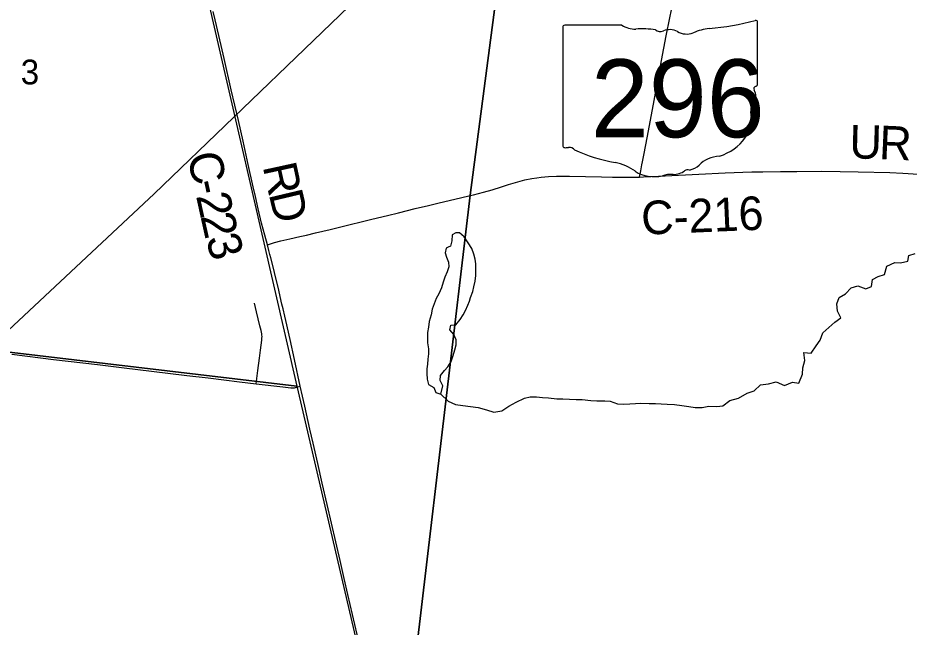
# Model space of a CAD drawing. Extents: x 0 to 1101, y 0 to 440.
# Drawn here: x 844.169 to 845.677, y 370.06 to 371.091 of the extents above; entities that cross this region are included whole.
import ezdxf

# ---------------------------------------------------------------- set-up
doc = ezdxf.new("R2010")
doc.units = 0
for name, color, linetype in [('GM_X_County_Road', 7, 'Continuous'), ('GM_X_County_Road_Text', 7, 'Continuous'), ('GM_X_Minor_Lake', 7, 'Continuous'), ('GM_X_Minor_River', 7, 'Continuous'), ('GM_X_Rail_Line', 7, 'Continuous'), ('GM_X_Section', 7, 'Continuous'), ('GM_X_Section_Text', 7, 'Continuous'), ('GM_X_State_Location', 7, 'Continuous'), ('GM_X_State_Route', 7, 'Continuous'), ('GM_X_State_Shield', 7, 'Continuous'), ('GM_X_Township', 7, 'Continuous'), ('GM_X_Township_Road', 7, 'Continuous')]:
    doc.layers.add(name, color=color, linetype=linetype)

msp = doc.modelspace()

# ---------------------------------------------------------------- linework, layer by layer
at = {"layer": 'GM_X_County_Road'}
for points in [[(844.5913, 370.7074), (844.5869, 370.7236), (844.5814, 370.744), (844.5758, 370.7682), (844.5712, 370.7888), (844.5675, 370.8052), (844.5588, 370.8433), (844.5503, 370.8828), (844.5423, 370.9179), (844.5302, 370.9694), (844.5179, 371.0226), (844.5129, 371.0444), (844.5028, 371.088), (844.4994, 371.1022)], [(845.221, 370.8219), (845.2279, 370.8223), (845.2531, 370.8235), (845.3212, 370.8271), (845.3658, 370.829), (845.4111, 370.8307), (845.4297, 370.8309), (845.4595, 370.8311), (845.4875, 370.8314), (845.5291, 370.8317), (845.5608, 370.8315), (845.5913, 370.831), (845.6447, 370.8296), (845.6665, 370.8285), (845.7198, 370.825)]]:
    msp.add_lwpolyline(points, dxfattribs=at)
at = {"layer": 'GM_X_Minor_Lake'}
for points in [[(844.8847, 370.4544), (844.888, 370.4684), (844.8839, 370.4776), (844.8844, 370.4863), (844.891, 370.4945), (844.8964, 370.5005), (844.9022, 370.5096), (844.9058, 370.5202), (844.9086, 370.5296), (844.9106, 370.5379), (844.9107, 370.5467), (844.9067, 370.5555), (844.9003, 370.5632), (844.902, 370.5715), (844.9103, 370.5717), (844.9173, 370.5811), (844.9227, 370.5887), (844.9263, 370.5962), (844.9306, 370.6053), (844.9333, 370.6117), (844.9353, 370.6181), (844.9389, 370.6283), (844.9409, 370.6363), (844.9429, 370.6457), (844.9438, 370.6556), (844.9441, 370.6753), (844.9431, 370.6829), (844.9409, 370.6913), (844.9372, 370.7009), (844.9309, 370.7108), (844.9242, 370.7208), (844.9164, 370.7273), (844.9103, 370.7278), (844.9042, 370.7241), (844.9036, 370.7139), (844.9012, 370.7052), (844.8973, 370.7034)], [(844.8973, 370.7034), (844.8936, 370.7018), (844.8923, 370.6939), (844.8945, 370.6863), (844.8978, 370.6779), (844.8985, 370.6699), (844.8957, 370.6616), (844.8914, 370.6525), (844.889, 370.6442), (844.8858, 370.6344), (844.8815, 370.6245), (844.8772, 370.6163), (844.8733, 370.6072), (844.8701, 370.5985), (844.8684, 370.5887), (844.8652, 370.5773), (844.864, 370.5678), (844.8623, 370.5591), (844.8621, 370.5413), (844.8638, 370.5314), (844.8637, 370.523), (844.8628, 370.5135), (844.8623, 370.5052), (844.8614, 370.4972), (844.8609, 370.4893), (844.8616, 370.4801), (844.8641, 370.471), (844.8731, 370.4656), (844.8764, 370.4575), (844.8847, 370.4544)]]:
    msp.add_lwpolyline(points, dxfattribs=at)
at = {"layer": 'GM_X_Minor_River'}
msp.add_lwpolyline([(844.8847, 370.4544), (844.8975, 370.4428), (844.9095, 370.4369), (844.9221, 370.4353), (844.9349, 370.4336), (844.9482, 370.4319), (844.9622, 370.4279), (844.9747, 370.4243), (844.988, 370.4264), (844.9999, 370.4342), (845.0125, 370.4412), (845.0266, 370.4479), (845.0362, 370.45), (845.0468, 370.4499), (845.057, 370.449), (845.0673, 370.4481), (845.0813, 370.4467), (845.0915, 370.4466), (845.1025, 370.4461), (845.1139, 370.4455), (845.1238, 370.4454), (845.1389, 370.4437), (845.1488, 370.4431), (845.1621, 370.4433), (845.1716, 370.4424), (845.184, 370.4381), (845.1935, 370.4376), (845.2045, 370.4382), (845.214, 370.4388), (845.2235, 370.4391), (845.2372, 370.4385), (845.2482, 370.4387), (845.2577, 370.4382), (845.2676, 370.4377), (845.2801, 370.4368), (845.2926, 370.4355), (845.3047, 370.4334), (845.3153, 370.4317), (845.3271, 370.432), (845.3385, 370.4341), (845.3518, 370.4339), (845.362, 370.4345), (845.3739, 370.4439), (845.3888, 370.4478), (845.403, 370.456), (845.4152, 370.4604), (845.426, 370.4701), (845.4396, 370.4722), (845.4522, 370.4751), (845.4662, 370.4692), (845.4799, 370.4747), (845.4905, 370.4734), (845.4968, 370.4881), (845.4977, 370.4991), (845.5006, 370.5116), (845.4989, 370.525), (845.5118, 370.524), (845.5199, 370.5361), (845.5265, 370.5459), (845.5312, 370.5583), (845.5416, 370.5673), (845.5516, 370.5763), (845.5616, 370.5837), (845.5561, 370.5952), (845.5551, 370.6074), (845.5587, 370.618), (845.5694, 370.6246), (845.5794, 370.6344), (845.5908, 370.6376), (845.6041, 370.6329), (845.6136, 370.6366), (845.6153, 370.6483), (845.6252, 370.6535), (845.6355, 370.6568), (845.6395, 370.6712), (845.6533, 370.6774), (845.6628, 370.6769), (845.675, 370.6798), (845.677, 370.6893), (845.6877, 370.6925)], dxfattribs=at)
at = {"layer": 'GM_X_Rail_Line'}
msp.add_lwpolyline([(844.1346, 370.5459), (844.3997, 370.7937), (844.8041, 371.1833), (845.1901, 371.5461), (845.4225, 371.7708), (845.5333, 371.8771), (845.5894, 371.9309), (845.6284, 371.9639), (845.6782, 371.9983), (845.7357, 372.0303), (845.789, 372.0514), (845.8324, 372.0633), (845.8796, 372.0733), (846.2786, 372.1146), (846.3759, 372.1225), (846.4631, 372.1257), (846.5327, 372.1208), (846.59, 372.1143), (846.7044, 372.0937), (846.8234, 372.0596), (847.2573, 371.9407)], dxfattribs=at)
at = {"layer": 'GM_X_Section'}
for points in [[(843.9352, 371.6074), (844.3881, 371.5681), (844.393, 371.547), (844.6414, 370.468), (843.8246, 370.5643)], [(843.8246, 370.5643), (844.6414, 370.468), (844.8139, 369.7283), (844.7837, 369.4496), (843.7228, 369.5896)]]:
    msp.add_lwpolyline(points, close=True, dxfattribs=at)
at = {"layer": 'GM_X_State_Route'}
for points in [[(844.9345, 370.7908), (844.9399, 370.7921), (844.9568, 370.7962), (844.9717, 370.8003), (844.9876, 370.8055), (844.9994, 370.8094), (845.0149, 370.8141), (845.027, 370.8171), (845.039, 370.8195), (845.0473, 370.8208), (845.0544, 370.8217), (845.0607, 370.8223), (845.0671, 370.8228), (845.0808, 370.8233), (845.1026, 370.8232), (845.1566, 370.8222), (845.1755, 370.8219), (845.1928, 370.8218), (845.2111, 370.8217), (845.221, 370.8219), (845.2231, 370.8323), (845.2252, 370.8428), (845.2262, 370.8477), (845.2282, 370.8588), (845.2344, 370.8911), (845.2457, 370.9516), (845.2583, 371.0194), (845.2661, 371.0609), (845.2722, 371.0914), (845.2752, 371.1048)], [(844.5913, 370.7074), (844.6036, 370.711), (844.614, 370.7138), (844.6294, 370.7173), (844.646, 370.7212), (844.6575, 370.7238), (844.6729, 370.7275), (844.6973, 370.7334), (844.7359, 370.7428), (844.7457, 370.7453), (844.7683, 370.7507), (844.7944, 370.757), (844.8131, 370.7613), (844.8415, 370.7686), (844.8638, 370.7739), (844.8818, 370.7783), (844.9181, 370.787), (844.9345, 370.7908)], [(844.1588, 370.5223), (844.2291, 370.5134), (844.3037, 370.5045), (844.3488, 370.4992), (844.395, 370.4937), (844.4548, 370.4861), (844.4912, 370.4819), (844.5443, 370.4755), (844.5723, 370.4721), (844.6173, 370.4667), (844.6309, 370.4655), (844.6349, 370.4654), (844.6372, 370.4655), (844.6391, 370.4659), (844.6424, 370.4668), (844.6466, 370.4682), (844.6373, 370.5133), (844.6298, 370.5472), (844.6225, 370.5793), (844.6208, 370.5865), (844.6178, 370.5992), (844.616, 370.607), (844.6094, 370.6354), (844.6039, 370.6577), (844.6026, 370.6631), (844.5969, 370.6854), (844.5955, 370.6908), (844.5938, 370.6978), (844.5913, 370.7074)], [(844.8109, 369.7447), (844.8096, 369.7503), (844.7936, 369.8225), (844.7813, 369.8796), (844.743, 370.048), (844.7274, 370.1152), (844.7213, 370.1425), (844.7144, 370.1728), (844.6922, 370.2678), (844.6841, 370.3036), (844.6765, 370.3369), (844.6685, 370.3714), (844.6632, 370.395), (844.6544, 370.4344), (844.6466, 370.4682)]]:
    msp.add_lwpolyline(points, dxfattribs=at)
at = {"layer": 'GM_X_State_Shield'}
for p, q in [((845.0913, 371.0753), (845.0913, 370.8752)), ((845.1911, 371.0788), (845.0946, 371.0788)), ((845.4209, 370.979), (845.4209, 371.0837)), ((845.4209, 370.9791), (845.4209, 370.979))]:
    msp.add_line(p, q, dxfattribs=at)
for centre, major_axis, start_param, end_param in [((845.0951, 371.0758), (0.00382, 0), 1.712693, 3.28349), ((845.2141, 371.102), (0.037, 0), 4.042523, 4.731795), ((845.3035, 371.3516), (0.3495, 0), 4.814394, 5.042369), ((845.4173, 371.0842), (0.00367, 0), 6.141152, 7.989035), ((845.2264, 370.9664), (0.133, 0), 1.404758, 1.657858), ((845.2565, 371.0768), (0.0107, 0), 3.836095, 5.185415), ((845.2722, 371.0537), (0.0222, 0), 0.950623, 2.079405), ((845.3009, 371.0854), (0.0267, 0), 4.081561, 5.145723), ((845.3481, 371.0176), (0.0703, 0), 1.699011, 2.107814), ((845.4201, 370.9714), (0.00568, 0), 1.883978, 3.671073), ((845.3839, 370.9581), (0.0341, 0), 5.934695, 6.695948), ((845.417, 370.9786), (0.00393, 0), 5.05454, 6.418171), ((845.4341, 370.9352), (0.0248, 0), 2.387724, 3.262537), ((845.3231, 370.9219), (0.0874, 0), 5.101752, 6.440018), ((845.0951, 370.8748), (0.00385, 0), 3.00124, 4.508301), ((845.0957, 370.8952), (0.0294, 0), 4.665946, 4.897461), ((845.1017, 370.8637), (0.0106, 0), 0.519207, 1.627899), ((845.2356, 371.0435), (0.2524, 0), 4.195997, 4.488961), ((845.3599, 370.819), (0.0479, 0), 1.647645, 2.488434), ((845.1603, 370.7853), (0.079, 0), 0.823519, 1.323587), ((845.3025, 370.8283), (0.00752, 0), 1.147584, 2.315152), ((845.2993, 370.8558), (0.0282, 0), 4.937069, 5.64225), ((845.2457, 370.8627), (0.0501, 0), 4.026481, 4.996735), ((845.2747, 370.7935), (0.0412, 0), 1.495662, 1.94098), ((845.2783, 370.8477), (0.0267, 0), 4.691044, 5.507374)]:
    msp.add_ellipse(centre, major_axis=major_axis, ratio=0.8, start_param=start_param, end_param=end_param, dxfattribs=at)
at = {"layer": 'GM_X_Township'}
for points in [[(843.7743, 376.6401), (844.4941, 376.5699), (845.4182, 376.4736), (845.5612, 376.461), (845.6523, 376.4464), (845.649, 376.3795), (845.6323, 376.2442), (845.56, 375.6723), (845.4198, 374.5609), (845.4081, 374.4677), (845.355, 374.0482), (845.2, 372.8166), (844.9343, 370.7914), (844.8107, 369.7452), (844.7764, 369.459), (844.7671, 369.3901), (844.6729, 368.4734), (843.0244, 368.6428)], [(849.9545, 374.031), (849.8439, 372.9428), (849.801, 372.4523), (849.7903, 372.3822), (849.6279, 370.8315), (849.4693, 369.1354), (849.458, 369.0211), (849.1756, 369.0468), (848.9835, 369.0702), (848.1881, 369.1294), (847.2656, 369.2256), (846.5466, 369.2884), (846.0672, 369.3302), (844.8955, 369.3794), (844.7671, 369.3901), (844.7764, 369.459), (844.8107, 369.7452), (844.9343, 370.7914), (845.2, 372.8166), (845.355, 374.0482)]]:
    msp.add_lwpolyline(points, dxfattribs=at)
at = {"layer": 'GM_X_Township_Road'}
msp.add_lwpolyline([(844.5723, 370.4721), (844.5749, 370.4948), (844.5777, 370.5157), (844.5795, 370.5292), (844.5817, 370.5458), (844.582, 370.5491), (844.5822, 370.5521), (844.582, 370.5546), (844.5818, 370.5569), (844.5813, 370.5597), (844.5806, 370.5624), (844.5788, 370.5703), (844.5731, 370.5937), (844.5693, 370.6088)], dxfattribs=at)

# ---------------------------------------------------------------- texts
at = {"layer": 'GM_X_County_Road_Text'}
for s, height, rotation, p in [('U', 0.0568, 358.5749, (845.5758, 370.8537)), ('R', 0.0568, 357.5549, (845.6257, 370.8525)), ('C', 0.0568, 282.2193, (844.4555, 370.8588)), ('R', 0.0568, 282.3188, (844.5832, 370.8402)), ('-', 0.0568, 282.2508, (844.4654, 370.8131)), ('2', 0.0568, 282.3056, (844.4704, 370.7903)), ('D', 0.0568, 283.3325, (844.5934, 370.7935)), ('C-216', 0.05682, 2.4613, (845.2251, 370.7242)), ('2', 0.0568, 282.5964, (844.4779, 370.7558)), ('3', 0.0568, 286.3022, (844.4866, 370.7177))]:
    msp.add_text(s, height=height, rotation=rotation, dxfattribs=at).set_placement(p)
at = {"layer": 'GM_X_Section_Text'}
msp.add_text('3', height=0.0419, rotation=0, dxfattribs=at).set_placement((844.1739, 370.9788))
at = {"layer": 'GM_X_State_Location'}
for s in ['s', 'r']:
    msp.add_text(s, height=0.000189, dxfattribs=at).set_placement((845.2524, 370.962))
msp.add_text('296', height=0.000189, rotation=0, dxfattribs=at).set_placement((845.1856, 370.9482))
at = {"layer": 'GM_X_State_Shield'}
msp.add_text('296', height=0.13184, dxfattribs=at).set_placement((845.1388, 370.8893))

doc.saveas('drawing.dxf')
